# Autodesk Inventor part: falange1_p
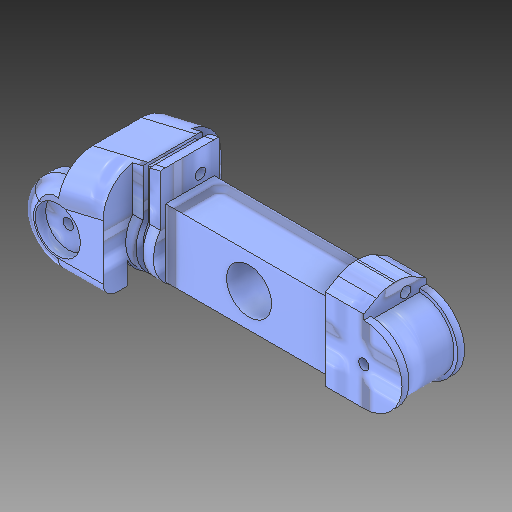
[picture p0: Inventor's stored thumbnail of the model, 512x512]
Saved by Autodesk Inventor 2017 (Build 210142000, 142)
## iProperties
Created: 2017-05
Part Number: falange1_p
Material: Generic
Document SubType Name: Modeling
Designer: alez_
Density: 1 g/cm^3
Appearance: Default
Author: alez_
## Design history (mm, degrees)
derived "Falange_1.ipt" dims "d0" = 9
feature "Solid1::Falange_1.ipt" dims "d0" = 9
tag "TaggingFeature1"
body "Solid1"
